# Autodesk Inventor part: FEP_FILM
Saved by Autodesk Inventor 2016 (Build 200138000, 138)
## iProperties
Created: 2016-01
Part Number: FEP_FILM
Material: Generic
Document SubType Name: Modeling
Designer: John
Density: 1 g/cm^3
Appearance: Default
Author: John
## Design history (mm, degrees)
feature "SOLID1"
body "Solid1"
